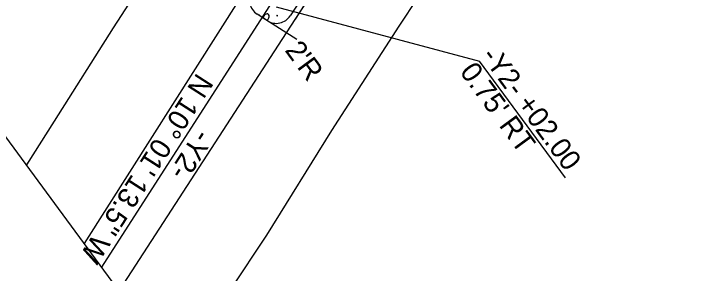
# Model space of a CAD drawing. Extents: x 1763480 to 1764420, y 711010 to 712012.
# Drawn here: x 1763772.3 to 1763855, y 711338.1 to 711369.7 of the extents above; entities that cross this region are included whole.
import ezdxf

# ---------------------------------------------------------------- set-up
doc = ezdxf.new("R2010")
doc.units = 0
for name, color, linetype in [('Old_Level_10', 7, 'Continuous'), ('Old_Level_11', 7, 'Continuous'), ('Prop Conc Island Cover', 7, 'Continuous'), ('Prop EOT', 7, 'Continuous'), ('Prop Grid Mask', 7, 'Continuous'), ('Prop Horizontal Alignment Direction Label', 7, 'Continuous'), ('Prop Horizontal Alignment Tick Small', 7, 'Continuous'), ('Prop Lane Lines', 7, 'Continuous'), ('Sheet Block Revision CELL', 7, 'Continuous')]:
    doc.layers.add(name, color=color, linetype=linetype)

msp = doc.modelspace()

# ---------------------------------------------------------------- linework, layer by layer
at = {"layer": 'Old_Level_10'}
for points in [[(1763802.193, 711369.551), (1763802.182, 711369.551), (1763802.178, 711369.539), (1763802.179, 711369.524)], [(1763802.255, 711369.475), (1763802.262, 711369.487), (1763802.26, 711369.509), (1763802.229, 711369.531), (1763802.205, 711369.54), (1763802.192, 711369.543)], [(1763802.825, 711369.5), (1763802.721, 711369.494), (1763802.67, 711369.346), (1763802.667, 711369.211)], [(1763803.132, 711368.912), (1763803.231, 711369.011), (1763803.373, 711369.218), (1763803.409, 711369.513), (1763803.254, 711369.749), (1763803.021, 711369.713), (1763802.868, 711369.608), (1763802.831, 711369.561)], [(1763804.356, 711369.559), (1763804.33, 711369.559), (1763804.327, 711369.482), (1763804.407, 711369.452), (1763804.427, 711369.513), (1763804.392, 711369.538), (1763804.368, 711369.546), (1763804.355, 711369.55)]]:
    msp.add_open_spline(points, degree=3, dxfattribs=at)
at = {"layer": 'Old_Level_11'}
msp.add_lwpolyline([(1763871.457, 711571.095), (1763982.563, 711419.98), (1763814.351, 711296.303), (1763703.244, 711447.418)], close=True, dxfattribs=at)
msp.add_lwpolyline([(1763871.457, 711571.095), (1763982.563, 711419.98), (1763814.351, 711296.303), (1763703.244, 711447.418)], close=True, dxfattribs=at)
msp.add_lwpolyline([(1763871.457, 711571.095), (1763982.563, 711419.98), (1763814.351, 711296.303), (1763703.244, 711447.418)], close=True, dxfattribs=at)
msp.add_lwpolyline([(1763871.457, 711571.095), (1763982.563, 711419.98), (1763814.351, 711296.303), (1763703.244, 711447.418)], close=True, dxfattribs=at)
at = {"layer": 'Prop Conc Island Cover'}
for p, q in [((1763830.806, 711408.185), (1763805.942, 711369.484)), ((1763803.178, 711368.882), (1763801.916, 711369.693))]:
    msp.add_line(p, q, dxfattribs=at)
for centre, start, end in [((1763802.997, 711371.376), 145.41273, 237.28041), ((1763804.259, 711370.565), 237.28041, 327.28041)]:
    msp.add_arc(centre, 2, start, end, dxfattribs=at)
at = {"layer": 'Prop EOT'}
for p, q in [((1763819.198, 711368.208), (1763827.151, 711380.307)), ((1763788.759, 711374.809), (1763784.414, 711368.014)), ((1763784.414, 711368.014), (1763777.254, 711356.67)), ((1763811.015, 711355.548), (1763819.198, 711368.208)), ((1763777.254, 711356.67), (1763773.872, 711351.358)), ((1763803.106, 711342.816), (1763811.015, 711355.548)), ((1763792.223, 711326.399), (1763803.106, 711342.816))]:
    msp.add_line(p, q, dxfattribs=at)
at = {"layer": 'Prop Grid Mask'}
for p in [(1763804.259, 711370.565), (1763839.439, 711349.769)]:
    msp.add_line(p, (1763828.99, 711363.98), dxfattribs=at)
at = {"layer": 'Prop Horizontal Alignment Tick Small'}
msp.add_line((1763806.754, 711366.585), (1763802.547, 711369.288), dxfattribs=at)
at = {"layer": 'Prop Lane Lines'}
for p, q in [((1763805.492, 711367.396), (1763831.437, 711407.78)), ((1763806.573, 711369.079), (1763831.437, 711407.78)), ((1763780.918, 711341.775), (1763800.553, 711372.676)), ((1763785.129, 711336.048), (1763805.492, 711367.396))]:
    msp.add_line(p, q, dxfattribs=at)
at = {"layer": 'Sheet Block Revision CELL'}
msp.add_line((1763783.028, 711338.906), (1763848.854, 711441.364), dxfattribs=at)

# ---------------------------------------------------------------- texts
at = {"layer": 'Prop Grid Mask'}
for s, p in [("2'R", (1763805.219, 711365.28)), ('-Y2- +02.00', (1763829.104, 711364.58)), ("0.75' RT", (1763826.486, 711362.654))]:
    msp.add_text(s, height=2.5, rotation=306.32498, dxfattribs=at).set_placement(p)
at = {"layer": 'Prop Horizontal Alignment Direction Label'}
for s, rotation, p in [('N 10%%d 01\' 13.5" W', 237.28041, (1763794.62, 711362.64)), ('-Y2-', 237.28431, (1763794.588, 711355.829))]:
    msp.add_text(s, height=2.5, rotation=rotation, dxfattribs=at).set_placement(p)

doc.saveas('drawing.dxf')
